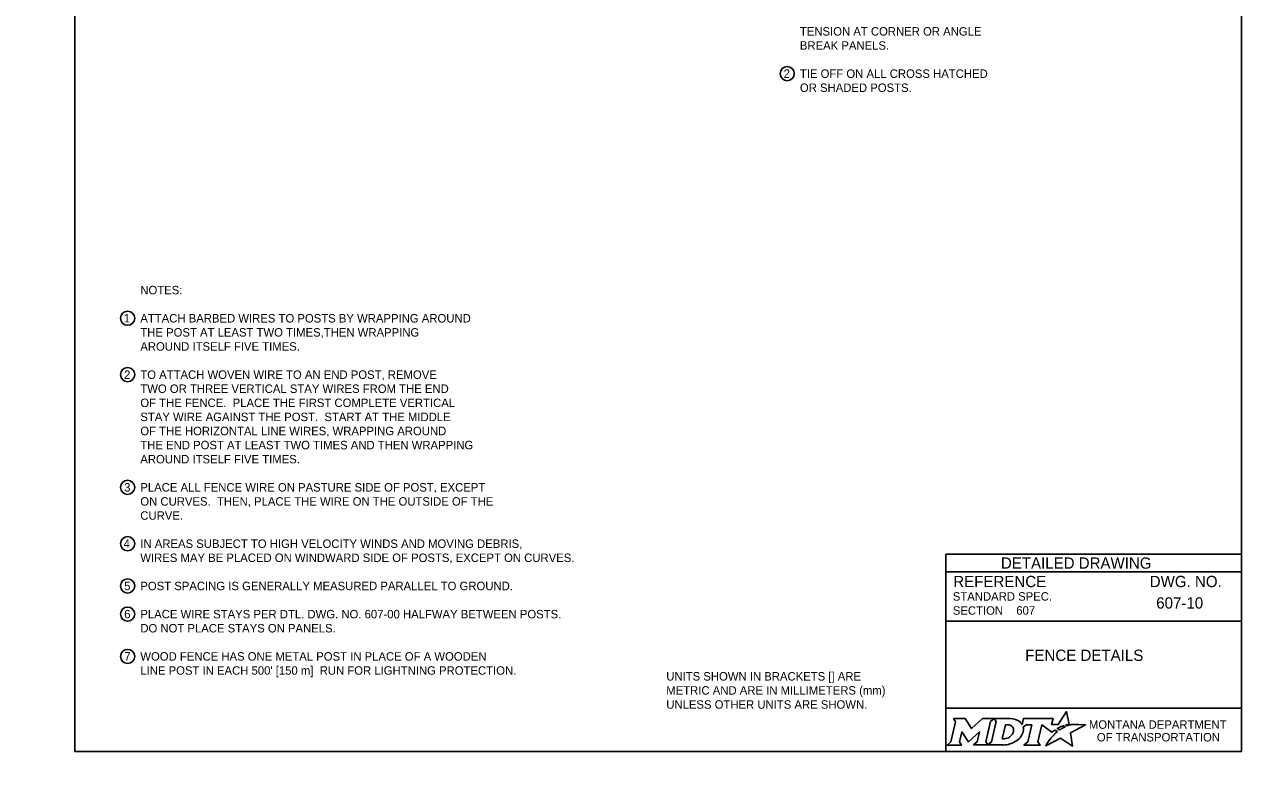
# Model space of a CAD drawing. Extents: x 49990.8 to 50021, y 49987.6 to 50011.4.
# Drawn here: x 49999.98 to 50008.61, y 49999.86 to 50005.22 of the extents above; entities that cross this region are included whole.
import ezdxf

# ---------------------------------------------------------------- set-up
doc = ezdxf.new("R2010")
doc.units = 0
for name, color, linetype in [('Level 1', 7, 'Continuous'), ('Level 2', 7, 'Continuous'), ('Level 5', 7, 'Continuous')]:
    doc.layers.add(name, color=color, linetype=linetype)

msp = doc.modelspace()

# ---------------------------------------------------------------- linework, layer by layer
at = {"layer": 'Level 1'}
msp.add_line((49999.9766, 49999.8624), (49999.9766, 49999.8624), dxfattribs=at)
msp.add_lwpolyline([(50008.6146, 50011.2628), (50000.3356, 50011.2628), (50000.3356, 50000.0624), (50008.6146, 50000.0624)], close=True, dxfattribs=at)
at = {"layer": 'Level 2'}
for p, q in [((50008.6146, 50001.4624), (50006.5146, 50001.4624)), ((50006.5146, 50001.4624), (50006.5146, 50000.0624)), ((50008.6146, 50001.3374), (50006.5146, 50001.3374)), ((50008.2507, 50001.1223), (50008.2507, 50001.1223)), ((50008.6146, 50000.9874), (50006.5146, 50000.9874)), ((50007.0089, 50001.0629), (50007.0089, 50001.0629)), ((50007.5646, 50000.7383), (50007.5646, 50000.7383)), ((50008.6146, 50000.3693), (50006.5146, 50000.3693))]:
    msp.add_line(p, q, dxfattribs=at)
for points in [[(50006.5701, 50000.2974), (50006.5842, 50000.274), (50006.5507, 50000.1307), (50006.525, 50000.1082), (50006.6266, 50000.1082), (50006.6131, 50000.131), (50006.6293, 50000.2011), (50006.673, 50000.1321), (50006.6783, 50000.1321), (50006.7534, 50000.2016), (50006.737, 50000.1305), (50006.7123, 50000.1085), (50006.8139, 50000.1085), (50006.8001, 50000.1318), (50006.8333, 50000.2742)], [(50006.8333, 50000.2742), (50006.8586, 50000.2974), (50006.7762, 50000.2974), (50006.6966, 50000.2244), (50006.6521, 50000.2971), (50006.5701, 50000.2974)], [(50006.9722, 50000.2974), (50006.8586, 50000.2974), (50006.8733, 50000.2745), (50006.8394, 50000.1307), (50006.8139, 50000.1085), (50006.9245, 50000.1085)], [(50007.3771, 50000.2447), (50007.3668, 50000.2503), (50007.3784, 50000.2531), (50007.39, 50000.2551), (50007.3726, 50000.3452), (50007.3131, 50000.2539), (50007.2658, 50000.2532), (50007.2761, 50000.2973), (50007.0669, 50000.2974), (50007.0568, 50000.2549), (50007.051, 50000.2632)], [(50006.9962, 50000.2107), (50006.995, 50000.2026), (50006.9918, 50000.1933), (50006.9876, 50000.1851), (50006.982, 50000.1776), (50006.9755, 50000.1707), (50006.9676, 50000.1644), (50006.9593, 50000.1597), (50006.9502, 50000.1558), (50006.9411, 50000.1535), (50006.9319, 50000.1526), (50006.916, 50000.1526), (50006.9396, 50000.2526), (50006.9556, 50000.2526), (50006.9632, 50000.252), (50006.9708, 50000.2501), (50006.9774, 50000.2471), (50006.9835, 50000.2429), (50006.9883, 50000.2379), (50006.992, 50000.2319), (50006.9947, 50000.2257), (50006.9963, 50000.2183), (50006.9963, 50000.2153), (50006.9962, 50000.2107)], [(50007.0636, 50000.2383), (50007.0882, 50000.2514), (50007.1251, 50000.2514), (50007.0965, 50000.1309), (50007.069, 50000.1082), (50007.1852, 50000.1082), (50007.1682, 50000.1311), (50007.1964, 50000.2513), (50007.2677, 50000.1996), (50007.2888, 50000.2147), (50007.3085, 50000.2038)], [(50007.2527, 50000.1479), (50007.2374, 50000.1235), (50007.2327, 50000.116), (50007.2269, 50000.1074), (50007.2246, 50000.1031), (50007.3299, 50000.1562), (50007.4138, 50000.1011), (50007.4007, 50000.1938), (50007.5076, 50000.2522), (50007.4583, 50000.253), (50007.4282, 50000.2534), (50007.4074, 50000.2537), (50007.4006, 50000.2522), (50007.3957, 50000.251), (50007.3873, 50000.2487), (50007.3771, 50000.2447)], [(50007.3267, 50000.2171), (50007.3243, 50000.2154), (50007.306, 50000.225), (50007.3163, 50000.2307), (50007.3204, 50000.2329), (50007.329, 50000.2369), (50007.3347, 50000.2395), (50007.3426, 50000.2425), (50007.3499, 50000.2452), (50007.3617, 50000.2378), (50007.3577, 50000.2357), (50007.3531, 50000.2332), (50007.3489, 50000.231), (50007.3439, 50000.2281), (50007.342, 50000.227), (50007.3393, 50000.2254), (50007.3368, 50000.224), (50007.3345, 50000.2224), (50007.3319, 50000.2206), (50007.3292, 50000.2188), (50007.3267, 50000.2171)], [(50006.9702, 50000.1158), (50006.9786, 50000.1184), (50006.9916, 50000.1238), (50007.012, 50000.1348)], [(50007.2666, 50000.164), (50007.2666, 50000.164)]]:
    msp.add_lwpolyline(points, dxfattribs=at)
for centre in [(50005.3899, 50004.8738), (50000.7096, 50003.1373), (50000.7096, 50002.7373), (50000.7096, 50001.9373), (50000.7096, 50001.5373), (50000.7096, 50001.2373), (50000.7096, 50001.0373), (50000.7096, 50000.7373)]:
    msp.add_circle(centre, 0.05, dxfattribs=at)
for centre, radius, start, end in [((50006.9953, 50000.219), 0.0709, 339.53292, 15.85821), ((50006.9513, 50000.2363), 0.1183, 300.91025, 339.13831)]:
    msp.add_arc(centre, radius, start, end, dxfattribs=at)
for centre, major_axis, ratio, start_param, end_param in [((50006.9701, 50000.25), (0.0834, -0.0037), 0.568097, 0.61298, 1.570796), ((50007.0257, 50000.2573), (0.0361, -0.0295), 0.469099, 1.225588, 1.570796), ((50007.2974, 50000.1941), (-0.0112, -0.0097), 0.021651, 3.157348, 6.283185), ((50006.9248, 50000.2568), (0, 0.1484), 0.987302, 3.139398, 3.456847), ((50007.2597, 50000.1559), (-0.00694, -0.00806), 0.008222, 0, 3.137361), ((50007.2764, 50000.1742), (-0.0098, -0.0102), 0.016458, 3.141593, 6.279097)]:
    msp.add_ellipse(centre, major_axis=major_axis, ratio=ratio, start_param=start_param, end_param=end_param, dxfattribs=at)

# ---------------------------------------------------------------- texts
for s, height, p in [('TENSION AT CORNER OR ANGLE ', 0.06, (50005.4799, 50005.1437)), ('BREAK PANELS.', 0.06, (50005.4799, 50005.0437)), ('2', 0.06, (50005.3648, 50004.8439)), ('TIE OFF ON ALL CROSS HATCHED ', 0.06, (50005.4799, 50004.8437)), ('OR SHADED POSTS.', 0.06, (50005.4799, 50004.7437)), ('NOTES:', 0.06, (50000.7996, 50003.3073)), ('1', 0.06, (50000.6816, 50003.1076)), ('ATTACH BARBED WIRES TO POSTS BY WRAPPING AROUND ', 0.06, (50000.7996, 50003.1073)), ('THE POST AT LEAST TWO TIMES,THEN WRAPPING ', 0.06, (50000.7996, 50003.0073)), ('AROUND ITSELF FIVE TIMES.', 0.06, (50000.7996, 50002.9073)), ('2', 0.06, (50000.6845, 50002.7074)), ('TO ATTACH WOVEN WIRE TO AN END POST, REMOVE ', 0.06, (50000.7996, 50002.7073)), ('TWO OR THREE VERTICAL STAY WIRES FROM THE END ', 0.06, (50000.7996, 50002.6073)), ('OF THE FENCE.  PLACE THE FIRST COMPLETE VERTICAL ', 0.06, (50000.7996, 50002.5073)), ('STAY WIRE AGAINST THE POST.  START AT THE MIDDLE ', 0.06, (50000.7996, 50002.4073)), ('OF THE HORIZONTAL LINE WIRES, WRAPPING AROUND', 0.06, (50000.7996, 50002.3073)), ('THE END POST AT LEAST TWO TIMES AND THEN WRAPPING ', 0.06, (50000.7996, 50002.2073)), ('AROUND ITSELF FIVE TIMES.', 0.06, (50000.7996, 50002.1073)), ('3', 0.06, (50000.6845, 50001.9074)), ('PLACE ALL FENCE WIRE ON PASTURE SIDE OF POST, EXCEPT', 0.06, (50000.7996, 50001.9073)), ('ON CURVES.  THEN, PLACE THE WIRE ON THE OUTSIDE OF THE', 0.06, (50000.7996, 50001.8073)), ('CURVE.', 0.06, (50000.7996, 50001.7073)), ('4', 0.06, (50000.6809, 50001.5073)), ('IN AREAS SUBJECT TO HIGH VELOCITY WINDS AND MOVING DEBRIS,', 0.06, (50000.7996, 50001.5073)), ('WIRES MAY BE PLACED ON WINDWARD SIDE OF POSTS, EXCEPT ON CURVES.', 0.06, (50000.7996, 50001.4073)), ('5', 0.06, (50000.6848, 50001.2074)), ('POST SPACING IS GENERALLY MEASURED PARALLEL TO GROUND.', 0.06, (50000.7996, 50001.2073)), ('REFERENCE', 0.08, (50006.5682, 50001.229)), ('DWG. NO.', 0.08, (50007.9624, 50001.229)), ('STANDARD SPEC.', 0.06, (50006.5649, 50001.133)), ('607-10', 0.08, (50008.0085, 50001.0767)), ('6', 0.06, (50000.6852, 50001.0074)), ('PLACE WIRE STAYS PER DTL. DWG. NO. 607-00 HALFWAY BETWEEN POSTS.', 0.06, (50000.7996, 50001.0073)), ('SECTION', 0.06, (50006.5649, 50001.033)), ('607', 0.06, (50007.0153, 50001.0335)), ('DO NOT PLACE STAYS ON PANELS.', 0.06, (50000.7996, 50000.9073)), ('7', 0.06, (50000.6859, 50000.7074)), ('WOOD FENCE HAS ONE METAL POST IN PLACE OF A WOODEN', 0.06, (50000.7996, 50000.7073)), ('FENCE DETAILS', 0.08, (50007.0787, 50000.7054)), ("LINE POST IN EACH 500' [150 m]  RUN FOR LIGHTNING PROTECTION.", 0.06, (50000.7996, 50000.6073)), ('UNITS SHOWN IN BRACKETS [] ARE ', 0.06, (50004.5316, 50000.5659)), ('METRIC AND ARE IN MILLIMETERS (mm) ', 0.06, (50004.5316, 50000.4659)), ('UNLESS OTHER UNITS ARE SHOWN.', 0.06, (50004.5316, 50000.3659)), ('MONTANA DEPARTMENT', 0.06, (50007.5308, 50000.2236)), ('OF TRANSPORTATION', 0.06, (50007.587, 50000.1336))]:
    msp.add_text(s, height=height, dxfattribs=at).set_placement(p)
at = {"layer": 'Level 5'}
msp.add_text('DETAILED DRAWING', height=0.0799, dxfattribs=at).set_placement((50006.9063, 50001.3599))

doc.saveas('drawing.dxf')
